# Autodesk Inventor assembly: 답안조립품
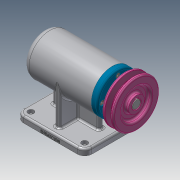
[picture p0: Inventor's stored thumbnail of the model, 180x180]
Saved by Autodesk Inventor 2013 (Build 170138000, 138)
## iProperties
Created: 2020-10
Part Number: 답안조립품
Document SubType Name: Assembly
Designer: user
Author: user
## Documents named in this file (12)
- C:\Users\user\Desktop\701004V1032\답안조립품.iam
- C:\Users\user\Desktop\701004V1032\본체.ipt
- C:\Users\user\Desktop\701004V1032\V벨트풀리.ipt
- C:\Users\user\Desktop\701004V1032\멈춤나사 M3.ipt
- C:\Users\user\Desktop\701004V1032\베어링 6004.ipt
- C:\Users\user\Desktop\701004V1032\베어링 51202.ipt
- C:\Users\user\Desktop\701004V1032\볼트 M4.ipt
- C:\Users\user\Desktop\701004V1032\어댑터슬리브.ipt
- C:\Users\user\Desktop\701004V1032\오일 실.ipt
- C:\Users\user\Desktop\701004V1032\축.ipt
- C:\Users\user\Desktop\701004V1032\커버.ipt
- C:\Users\user\Desktop\701004V1032\키 5 x 5 x 16.ipt
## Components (1 placed, 1 different names)
1. V벨트풀리:1 — 플러쉬:1
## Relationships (1: Flush 1)
- 플러쉬:1 [Flush]: V벨트풀리:1
